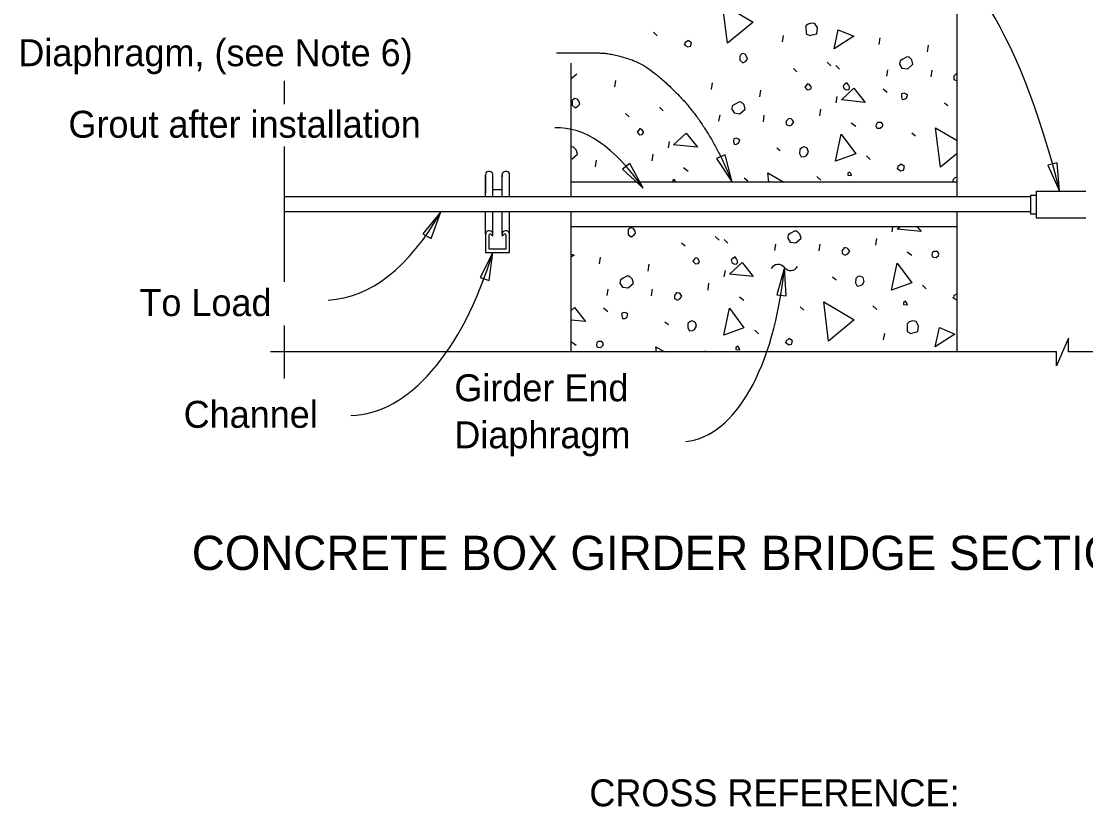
# Model space of a CAD drawing. Extents: x 112544 to 112597.1, y 111084 to 111107.1.
# Drawn here: x 112563.53 to 112569.51, y 111095.74 to 111100.15 of the extents above; entities that cross this region are included whole.
import ezdxf

# ---------------------------------------------------------------- set-up
doc = ezdxf.new("R2010")
doc.units = 0
for name, color, linetype in [('Dimension', 7, 'Continuous'), ('Lighting', 7, 'Continuous'), ('Miscellaneous', 7, 'Continuous'), ('SupstrConc', 7, 'Continuous'), ('TextStructures', 7, 'Continuous')]:
    doc.layers.add(name, color=color, linetype=linetype)

msp = doc.modelspace()

# ---------------------------------------------------------------- linework, layer by layer
at = {"layer": 'Dimension'}
for points in [[(112565.0089, 111099.6803), (112565.0089, 111099.8109)], [(112565.0089, 111098.684), (112565.0089, 111099.4429)], [(112565.0089, 111098.1405), (112565.0089, 111098.4381)], [(112572.7335, 111098.2898), (112569.4119, 111098.2898), (112569.4119, 111098.3673), (112569.3781, 111098.2898), (112569.3444, 111098.2123), (112569.3444, 111098.2898), (112564.9314, 111098.2898)]]:
    msp.add_lwpolyline(points, dxfattribs=at)
for points in [[(112567.5225, 111099.2426), (112567.484, 111099.3962), (112567.4356, 111099.375)], [(112567.0238, 111099.208), (112566.9489, 111099.3476), (112566.9071, 111099.3152)], [(112569.3609, 111099.1927), (112569.3473, 111099.3505), (112569.2961, 111099.3372)], [(112565.8871, 111099.0759), (112565.7873, 111098.9529), (112565.8334, 111098.9269)], [(112566.1803, 111098.8483), (112566.1085, 111098.7071), (112566.1591, 111098.6913)], [(112567.8166, 111098.7635), (112567.7739, 111098.611), (112567.8266, 111098.6054)]]:
    msp.add_lwpolyline(points, close=True, dxfattribs=at)
for centre, start, end in [((112567.7809, 111098.7359), 38.18218, 149.9094), ((112567.8512, 111098.7912), 218.18218, 329.9094)]:
    msp.add_arc(centre, 0.0447, start, end, dxfattribs=at)
for centre, major_axis, ratio, start_param, end_param in [((112568.3781, 111096.9697), (-0.0172, -3.681), 0.331804, 2.220726, 3.141608), ((112566.6822, 111096.3591), (0.1544, -3.1879), 0.324138, 2.660287, 3.141582), ((112565.1442, 111100.9487), (-0.1111, 2.3674), 0.464296, 3.141604, 3.778402), ((112565.307, 111100.1396), (-0.0751, 2.2066), 0.468341, 3.141584, 4.071496), ((112567.0728, 111099.4077), (-0.1909, 1.6213), 0.453794, 3.141619, 4.251067)]:
    msp.add_ellipse(centre, major_axis=major_axis, ratio=ratio, start_param=start_param, end_param=end_param, dxfattribs=at)
msp.add_open_spline([(112566.5373, 111099.9674), (112566.7133, 111099.9674), (112566.844, 111099.9674), (112567.0703, 111099.892), (112567.4022, 111099.5398), (112567.5225, 111099.2426)], degree=2, dxfattribs=at)
at = {"layer": 'Lighting'}
for p, q in [((112566.1381, 111099.1593), (112566.1381, 111099.2843)), ((112566.1381, 111099.2843), (112566.1381, 111099.1817)), ((112566.1797, 111099.2886), (112566.1776, 111099.2925)), ((112566.1797, 111099.2726), (112566.1797, 111099.2886)), ((112566.1797, 111099.1593), (112566.1797, 111099.2843)), ((112566.234, 111099.2925), (112566.2319, 111099.2886)), ((112566.2319, 111099.2886), (112566.2319, 111099.2726)), ((112566.2319, 111099.1593), (112566.2319, 111099.2843)), ((112566.2735, 111099.1593), (112566.2735, 111099.2843)), ((112569.197, 111099.1593), (112565.0089, 111099.1593)), ((112566.2319, 111099.2003), (112566.1797, 111099.2003)), ((112569.197, 111099.1697), (112569.197, 111099.0655)), ((112569.197, 111099.1697), (112569.2304, 111099.1697)), ((112569.2304, 111099.1927), (112569.5079, 111099.1927)), ((112569.2304, 111099.1926), (112569.2304, 111099.0427)), ((112569.197, 111099.0759), (112565.0089, 111099.0759)), ((112566.1381, 111098.951), (112566.1381, 111099.076)), ((112566.1797, 111098.951), (112566.1797, 111099.076)), ((112566.2319, 111098.951), (112566.2319, 111099.076)), ((112566.2735, 111098.951), (112566.2735, 111099.076)), ((112569.197, 111099.0655), (112569.2304, 111099.0655)), ((112569.2304, 111099.0428), (112569.5079, 111099.0428)), ((112566.1381, 111098.951), (112566.1381, 111098.8484)), ((112566.1589, 111098.867), (112566.1589, 111098.9466)), ((112566.1678, 111098.9499), (112566.1797, 111098.9393)), ((112566.1797, 111098.9553), (112566.1776, 111098.9592)), ((112566.1797, 111098.9393), (112566.1797, 111098.9553)), ((112566.234, 111098.9592), (112566.2319, 111098.9553)), ((112566.2319, 111098.9553), (112566.2319, 111098.9393)), ((112566.2319, 111098.9393), (112566.2438, 111098.9499)), ((112566.2527, 111098.9466), (112566.2527, 111098.867)), ((112566.2735, 111098.8484), (112566.2735, 111098.951)), ((112566.2527, 111098.867), (112566.1589, 111098.867)), ((112566.1381, 111098.8484), (112566.2735, 111098.8484))]:
    msp.add_line(p, q, dxfattribs=at)
for centre, major_axis, start_param, end_param in [((112566.1589, 111099.2843), (-0.0208, 0), 3.598509, 6.283184), ((112566.2527, 111099.2843), (0.0208, 0), 0.000002, 2.684677), ((112566.1589, 111098.951), (-0.0208, 0), 3.598509, 6.283184), ((112566.1641, 111098.9466), (-0.0052, 0), 3.926991, 6.283185), ((112566.2527, 111098.951), (0.0208, 0), 0.000002, 2.684677), ((112566.2475, 111098.9466), (0.0052, 0), 6.283185, 8.63938)]:
    msp.add_ellipse(centre, major_axis=major_axis, ratio=0.8951, start_param=start_param, end_param=end_param, dxfattribs=at)
at = {"layer": 'Miscellaneous'}
for p, q in [((112567.082, 111100.0839), (112567.1029, 111100.0637)), ((112567.8058, 111100.0294), (112567.8118, 111100.0647)), ((112568.3482, 111100.0143), (112568.3536, 111100.0519)), ((112568.6205, 111099.9734), (112568.6259, 111100.011)), ((112567.8665, 111099.88), (112567.8868, 111099.8622)), ((112568.0563, 111099.9153), (112568.0773, 111099.8951)), ((112568.1051, 111099.8974), (112568.1261, 111099.8771)), ((112568.3906, 111099.8367), (112568.3966, 111099.872)), ((112568.6399, 111099.8336), (112568.6453, 111099.8713)), ((112566.864, 111099.777), (112566.8701, 111099.8123)), ((112567.4064, 111099.7619), (112567.4118, 111099.7996)), ((112567.6787, 111099.721), (112567.6842, 111099.7587)), ((112568.3705, 111099.7666), (112568.3939, 111099.747)), ((112568.1068, 111099.6882), (112568.1129, 111099.7235)), ((112567.1145, 111099.663), (112567.1355, 111099.6427)), ((112568.0153, 111099.6145), (112568.0207, 111099.6522)), ((112568.7151, 111099.6881), (112568.7347, 111099.6727)), ((112566.9247, 111099.6277), (112566.945, 111099.6098)), ((112567.4488, 111099.5843), (112567.4549, 111099.6196)), ((112567.6981, 111099.5812), (112567.7035, 111099.6189)), ((112568.1912, 111099.5762), (112568.217, 111099.5572)), ((112568.5323, 111099.5201), (112568.5526, 111099.5022)), ((112567.165, 111099.4358), (112567.1711, 111099.4711)), ((112567.0735, 111099.3621), (112567.0789, 111099.3998)), ((112567.7733, 111099.4358), (112567.793, 111099.4203)), ((112566.7563, 111099.3289), (112566.7617, 111099.3666)), ((112568.2774, 111099.3897), (112568.2984, 111099.3694)), ((112567.2494, 111099.3239), (112567.2752, 111099.3049)), ((112567.998, 111099.2734), (112568.0213, 111099.2538)), ((112568.7858, 111099.2426), (112566.6191, 111099.2426)), ((112567.5906, 111099.2677), (112567.6109, 111099.2499)), ((112568.7858, 111098.9927), (112566.6191, 111098.9927)), ((112568.4207, 111098.9633), (112568.4258, 111098.9927)), ((112567.4284, 111098.9381), (112567.4494, 111098.9179)), ((112567.4773, 111098.9201), (112567.4982, 111098.8999)), ((112568.3292, 111098.8896), (112568.3346, 111098.9273)), ((112567.2386, 111098.9028), (112567.2589, 111098.8849)), ((112567.7627, 111098.8595), (112567.7688, 111098.8947)), ((112568.012, 111098.8564), (112568.0174, 111098.8941)), ((112566.7785, 111098.7847), (112566.7839, 111098.8224)), ((112568.5051, 111098.8513), (112568.5309, 111098.8324)), ((112567.0509, 111098.7438), (112567.0563, 111098.7815)), ((112567.479, 111098.711), (112567.485, 111098.7462)), ((112567.3874, 111098.6373), (112567.3928, 111098.6749)), ((112568.0872, 111098.7109), (112568.1069, 111098.6954)), ((112566.8209, 111098.6071), (112566.827, 111098.6424)), ((112567.0702, 111098.604), (112567.0756, 111098.6417)), ((112568.5913, 111098.6648), (112568.6123, 111098.6445)), ((112567.5633, 111098.599), (112567.5891, 111098.58)), ((112566.8009, 111098.537), (112566.8242, 111098.5174)), ((112567.9045, 111098.5429), (112567.9248, 111098.525)), ((112568.3119, 111098.5485), (112568.3353, 111098.5289)), ((112567.1454, 111098.4585), (112567.1651, 111098.4431)), ((112567.6495, 111098.4124), (112567.6705, 111098.3922)), ((112568.3733, 111098.3579), (112568.3794, 111098.3932)), ((112566.6215, 111098.3466), (112566.6473, 111098.3277)), ((112566.9627, 111098.2905), (112566.9634, 111098.2899)), ((112567.3701, 111098.2961), (112567.3776, 111098.2899))]:
    msp.add_line(p, q, dxfattribs=at)
for points in [[(112567.4972, 111100.0218), (112567.4693, 111100.242), (112567.6414, 111100.1406), (112567.4972, 111100.0218)], [(112567.9371, 111100.1189), (112567.9384, 111100.0753), (112567.9592, 111100.0653), (112567.9713, 111100.0686), (112567.9978, 111100.0757), (112568.0021, 111100.1079), (112567.9878, 111100.1325), (112567.9689, 111100.1352), (112567.9496, 111100.13), (112567.9371, 111100.1189)], [(112568.0957, 111099.9906), (112568.1187, 111100.0977), (112568.2061, 111100.0616), (112568.0957, 111099.9906)], [(112567.2566, 111100.0117), (112567.275, 111100.0011), (112567.2895, 111100.0049), (112567.2946, 111100.0244), (112567.2756, 111100.0374), (112567.2672, 111100.03), (112567.2582, 111100.025), (112567.2566, 111100.0117), (112567.2553, 111100.0165)], [(112567.567, 111099.9447), (112567.5667, 111099.9265), (112567.5833, 111099.9129), (112567.5989, 111099.9222), (112567.6091, 111099.9327), (112567.6058, 111099.9448), (112567.5965, 111099.9604), (112567.5801, 111099.9637), (112567.5675, 111099.9526), (112567.567, 111099.9447)], [(112568.4628, 111099.9052), (112568.4765, 111099.883), (112568.5087, 111099.8787), (112568.538, 111099.9047), (112568.5315, 111099.9288), (112568.5143, 111099.9449), (112568.5015, 111099.9441), (112568.4811, 111099.9334), (112568.4655, 111099.9241), (112568.4628, 111099.9052)], [(112566.6513, 111099.8485), (112566.6191, 111099.8219)], [(112568.7684, 111099.837), (112568.7681, 111099.8188), (112568.7858, 111099.8106)], [(112568.7858, 111099.8517), (112568.7851, 111099.8518), (112568.7803, 111099.8505), (112568.7684, 111099.837)], [(112567.9307, 111099.7756), (112567.9449, 111099.7613), (112567.96, 111099.7627), (112567.9677, 111099.7726), (112567.9665, 111099.7774), (112567.9577, 111099.7906), (112567.9461, 111099.7952), (112567.9384, 111099.7854), (112567.9307, 111099.7756)], [(112568.1363, 111099.7038), (112568.2067, 111099.7693), (112568.2693, 111099.6903), (112568.1363, 111099.7038)], [(112568.1497, 111099.7696), (112568.1596, 111099.7618), (112568.1729, 111099.7602), (112568.1813, 111099.7677), (112568.1811, 111099.778), (112568.1755, 111099.7894), (112568.1674, 111099.8002), (112568.1542, 111099.7915), (112568.1458, 111099.784), (112568.1497, 111099.7696)], [(112566.6253, 111099.6924), (112566.625, 111099.6742), (112566.6416, 111099.6605), (112566.6572, 111099.6699), (112566.6673, 111099.6803), (112566.6641, 111099.6924), (112566.6547, 111099.708), (112566.6383, 111099.7114), (112566.6257, 111099.7003), (112566.6253, 111099.6924)], [(112567.521, 111099.6529), (112567.5347, 111099.6307), (112567.5669, 111099.6263), (112567.5962, 111099.6523), (112567.5897, 111099.6765), (112567.5725, 111099.6925), (112567.5598, 111099.6917), (112567.5393, 111099.6811), (112567.5237, 111099.6717), (112567.521, 111099.6529)], [(112568.4731, 111099.7216), (112568.477, 111099.7071), (112568.4898, 111099.708), (112568.5012, 111099.7136), (112568.507, 111099.7307), (112568.5002, 111099.7366), (112568.4886, 111099.7413), (112568.4741, 111099.7374), (112568.4731, 111099.7216)], [(112567.8266, 111099.5846), (112567.8263, 111099.5664), (112567.844, 111099.5582), (112567.8578, 111099.5645), (112567.8691, 111099.5805), (112567.861, 111099.5913), (112567.8543, 111099.5972), (112567.8433, 111099.5995), (112567.8385, 111099.5982), (112567.8266, 111099.5846)], [(112568.3329, 111099.5495), (112568.3391, 111099.5459), (112568.3548, 111099.545), (112568.3674, 111099.5561), (112568.3703, 111099.5647), (112568.3616, 111099.5779), (112568.3409, 111099.5775), (112568.3326, 111099.5701), (112568.3303, 111099.5591), (112568.3329, 111099.5495)], [(112566.9889, 111099.5232), (112567.0031, 111099.5089), (112567.0183, 111099.5104), (112567.026, 111099.5202), (112567.0247, 111099.525), (112567.016, 111099.5382), (112567.0044, 111099.5429), (112566.9966, 111099.5331), (112566.9889, 111099.5232)], [(112567.1945, 111099.4515), (112567.265, 111099.517), (112567.3275, 111099.438), (112567.1945, 111099.4515)], [(112568.1038, 111099.3613), (112568.1359, 111099.5122), (112568.2172, 111099.402), (112568.1038, 111099.3613)], [(112568.6926, 111099.3275), (112568.6647, 111099.5478), (112568.7858, 111099.4764)], [(112567.5314, 111099.4693), (112567.5353, 111099.4548), (112567.548, 111099.4556), (112567.5594, 111099.4613), (112567.5652, 111099.4783), (112567.5584, 111099.4843), (112567.5468, 111099.489), (112567.5323, 111099.4851), (112567.5314, 111099.4693)], [(112566.6191, 111099.3748), (112566.6252, 111099.374), (112566.6544, 111099.4), (112566.648, 111099.4241), (112566.6307, 111099.4402), (112566.6191, 111099.4394)], [(112567.9026, 111099.4264), (112567.9012, 111099.4027), (112567.9112, 111099.3847), (112567.9288, 111099.3868), (112567.9402, 111099.3925), (112567.9508, 111099.4108), (112567.945, 111099.4326), (112567.9272, 111099.4408), (112567.9152, 111099.4375), (112567.9026, 111099.4264)], [(112568.7858, 111099.4043), (112568.6926, 111099.3275)], [(112568.4521, 111099.3174), (112568.4704, 111099.3068), (112568.4849, 111099.3107), (112568.49, 111099.3302), (112568.471, 111099.3432), (112568.4627, 111099.3358), (112568.4536, 111099.3308), (112568.4521, 111099.3174), (112568.4508, 111099.3222)], [(112567.7296, 111099.2426), (112567.7229, 111099.2954), (112567.8126, 111099.2426)], [(112568.1719, 111099.2812), (112568.1931, 111099.2791), (112568.1906, 111099.2887), (112568.1825, 111099.2995), (112568.1717, 111099.2915), (112568.1719, 111099.2812)], [(112567.1904, 111099.2426), (112567.1941, 111099.2599), (112567.2068, 111099.2426)], [(112568.7625, 111099.2505), (112568.7623, 111099.2426)], [(112568.7858, 111099.2674), (112568.7755, 111099.2695), (112568.7629, 111099.2583), (112568.7625, 111099.2505)], [(112566.9392, 111098.9675), (112566.9389, 111098.9493), (112566.9555, 111098.9356), (112566.9711, 111098.945), (112566.9812, 111098.9555), (112566.978, 111098.9675), (112566.9686, 111098.9831), (112566.9522, 111098.9865), (112566.9396, 111098.9754), (112566.9392, 111098.9675)], [(112568.4502, 111098.979), (112568.465, 111098.9927)], [(112568.5616, 111098.9927), (112568.5832, 111098.9654), (112568.4502, 111098.979)], [(112567.8349, 111098.928), (112567.8486, 111098.9058), (112567.8808, 111098.9015), (112567.9101, 111098.9274), (112567.9037, 111098.9516), (112567.8864, 111098.9677), (112567.8737, 111098.9668), (112567.8532, 111098.9562), (112567.8376, 111098.9468), (112567.8349, 111098.928)], [(112568.1405, 111098.8597), (112568.1402, 111098.8415), (112568.1579, 111098.8334), (112568.1718, 111098.8397), (112568.183, 111098.8556), (112568.1749, 111098.8664), (112568.1682, 111098.8723), (112568.1572, 111098.8746), (112568.1524, 111098.8733), (112568.1405, 111098.8597)], [(112566.6191, 111098.8392), (112566.6364, 111098.832), (112566.6191, 111098.8209)], [(112567.3028, 111098.7984), (112567.317, 111098.784), (112567.3322, 111098.7855), (112567.3399, 111098.7953), (112567.3386, 111098.8002), (112567.3299, 111098.8134), (112567.3183, 111098.818), (112567.3106, 111098.8082), (112567.3028, 111098.7984)], [(112567.5219, 111098.7923), (112567.5317, 111098.7846), (112567.5451, 111098.783), (112567.5534, 111098.7904), (112567.5533, 111098.8007), (112567.5476, 111098.8122), (112567.5395, 111098.823), (112567.5263, 111098.8142), (112567.518, 111098.8068), (112567.5219, 111098.7923)], [(112568.6468, 111098.8246), (112568.653, 111098.8211), (112568.6687, 111098.8201), (112568.6813, 111098.8312), (112568.6842, 111098.8398), (112568.6755, 111098.853), (112568.6549, 111098.8526), (112568.6465, 111098.8452), (112568.6443, 111098.8343), (112568.6468, 111098.8246)], [(112567.5084, 111098.7266), (112567.5789, 111098.7921), (112567.6414, 111098.7131), (112567.5084, 111098.7266)], [(112568.4177, 111098.6364), (112568.4498, 111098.7873), (112568.5311, 111098.6771), (112568.4177, 111098.6364)], [(112566.8931, 111098.6756), (112566.9069, 111098.6534), (112566.9391, 111098.6491), (112566.9683, 111098.6751), (112566.9619, 111098.6992), (112566.9446, 111098.7153), (112566.9319, 111098.7145), (112566.9115, 111098.7038), (112566.8959, 111098.6945), (112566.8931, 111098.6756)], [(112568.2165, 111098.7015), (112568.2151, 111098.6779), (112568.2251, 111098.6598), (112568.2427, 111098.6619), (112568.2541, 111098.6676), (112568.2647, 111098.686), (112568.2589, 111098.7077), (112568.2412, 111098.7159), (112568.2291, 111098.7127), (112568.2165, 111098.7015)], [(112567.1987, 111098.6074), (112567.1984, 111098.5892), (112567.2161, 111098.581), (112567.23, 111098.5873), (112567.2412, 111098.6033), (112567.2332, 111098.614), (112567.2264, 111098.62), (112567.2154, 111098.6222), (112567.2106, 111098.6209), (112567.1987, 111098.6074)], [(112568.7858, 111098.6177), (112568.7849, 111098.6183), (112568.7766, 111098.6109), (112568.7676, 111098.6059), (112568.766, 111098.5925), (112568.7647, 111098.5974)], [(112568.0648, 111098.3503), (112568.0368, 111098.5706), (112568.2089, 111098.4691), (112568.0648, 111098.3503)], [(112568.4858, 111098.5563), (112568.5071, 111098.5542), (112568.5045, 111098.5639), (112568.4964, 111098.5746), (112568.4856, 111098.5666), (112568.4858, 111098.5563)], [(112568.766, 111098.5925), (112568.7843, 111098.5819), (112568.7858, 111098.5823)], [(112566.6191, 111098.523), (112566.6371, 111098.5397), (112566.6997, 111098.4607), (112566.6191, 111098.4689)], [(112566.9035, 111098.4921), (112566.9074, 111098.4776), (112566.9201, 111098.4784), (112566.9315, 111098.484), (112566.9373, 111098.5011), (112566.9305, 111098.5071), (112566.9189, 111098.5117), (112566.9045, 111098.5078), (112566.9035, 111098.4921)], [(112567.476, 111098.384), (112567.508, 111098.535), (112567.5893, 111098.4248), (112567.476, 111098.384)], [(112567.2748, 111098.4492), (112567.2733, 111098.4255), (112567.2833, 111098.4075), (112567.3009, 111098.4096), (112567.3123, 111098.4152), (112567.3229, 111098.4336), (112567.3171, 111098.4554), (112567.2994, 111098.4635), (112567.2873, 111098.4603), (112567.2748, 111098.4492)], [(112568.5046, 111098.4474), (112568.506, 111098.4038), (112568.5267, 111098.3938), (112568.5388, 111098.3971), (112568.5654, 111098.4042), (112568.5697, 111098.4364), (112568.5553, 111098.461), (112568.5365, 111098.4637), (112568.5172, 111098.4586), (112568.5046, 111098.4474)], [(112568.6632, 111098.3191), (112568.6863, 111098.4262), (112568.7736, 111098.3901), (112568.6632, 111098.3191)], [(112566.7633, 111098.3199), (112566.7694, 111098.3164), (112566.7852, 111098.3154), (112566.7977, 111098.3265), (112566.8006, 111098.3351), (112566.7919, 111098.3483), (112566.7713, 111098.3479), (112566.7629, 111098.3405), (112566.7607, 111098.3296), (112566.7633, 111098.3199)], [(112567.0986, 111098.2899), (112567.095, 111098.3182), (112567.1431, 111098.2899)], [(112567.544, 111098.3039), (112567.5653, 111098.3019), (112567.5627, 111098.3115), (112567.5546, 111098.3223), (112567.5439, 111098.3142), (112567.544, 111098.3039)], [(112567.8242, 111098.3402), (112567.8426, 111098.3296), (112567.857, 111098.3334), (112567.8622, 111098.3529), (112567.8432, 111098.366), (112567.8348, 111098.3585), (112567.8258, 111098.3535), (112567.8242, 111098.3402), (112567.8229, 111098.345)], [(112568.1593, 111098.2899), (112568.1476, 111098.2922), (112568.1449, 111098.2899)]]:
    msp.add_lwpolyline(points, dxfattribs=at)
at = {"layer": 'SupstrConc'}
for p, q in [((112568.7858, 111099.1593), (112568.7858, 111102.7452)), ((112566.6191, 111099.1593), (112566.6191, 111099.9108)), ((112566.6191, 111098.2899), (112566.6191, 111099.0759)), ((112568.7858, 111098.2899), (112568.7858, 111099.0759))]:
    msp.add_line(p, q, dxfattribs=at)

# ---------------------------------------------------------------- texts
at = {"layer": 'Dimension'}
for s, p in [('Diaphragm, (see Note 6)', (112563.5155, 111099.8934)), ('Girder End', (112565.9633, 111098.0131)), ('Diaphragm', (112565.9633, 111097.7491)), ('CROSS REFERENCE:', (112566.7213, 111095.7401))]:
    msp.add_text(s, height=0.1512, dxfattribs=at).set_placement(p)
at = {"layer": 'TextStructures'}
for s, height, p in [('Grout after installation', 0.1512, (112563.7968, 111099.492)), ('To Load', 0.1512, (112564.195, 111098.4909)), ('Channel', 0.1512, (112564.4434, 111097.8641)), ('CONCRETE BOX GIRDER BRIDGE SECTION THRU END BENTS', 0.192, (112564.4892, 111097.0664))]:
    msp.add_text(s, height=height, dxfattribs=at).set_placement(p)

doc.saveas('drawing.dxf')
